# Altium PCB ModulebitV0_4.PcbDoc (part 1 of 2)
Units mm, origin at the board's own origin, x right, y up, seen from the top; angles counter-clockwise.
Board outline 60 x 54 mm, 2 copper layers (Top Layer, Bottom Layer), stack 1.671 mm thick; 125 components, 87 nets, 543 pads, 469 vias.
Unrouted connection lines stored in the file: 1.
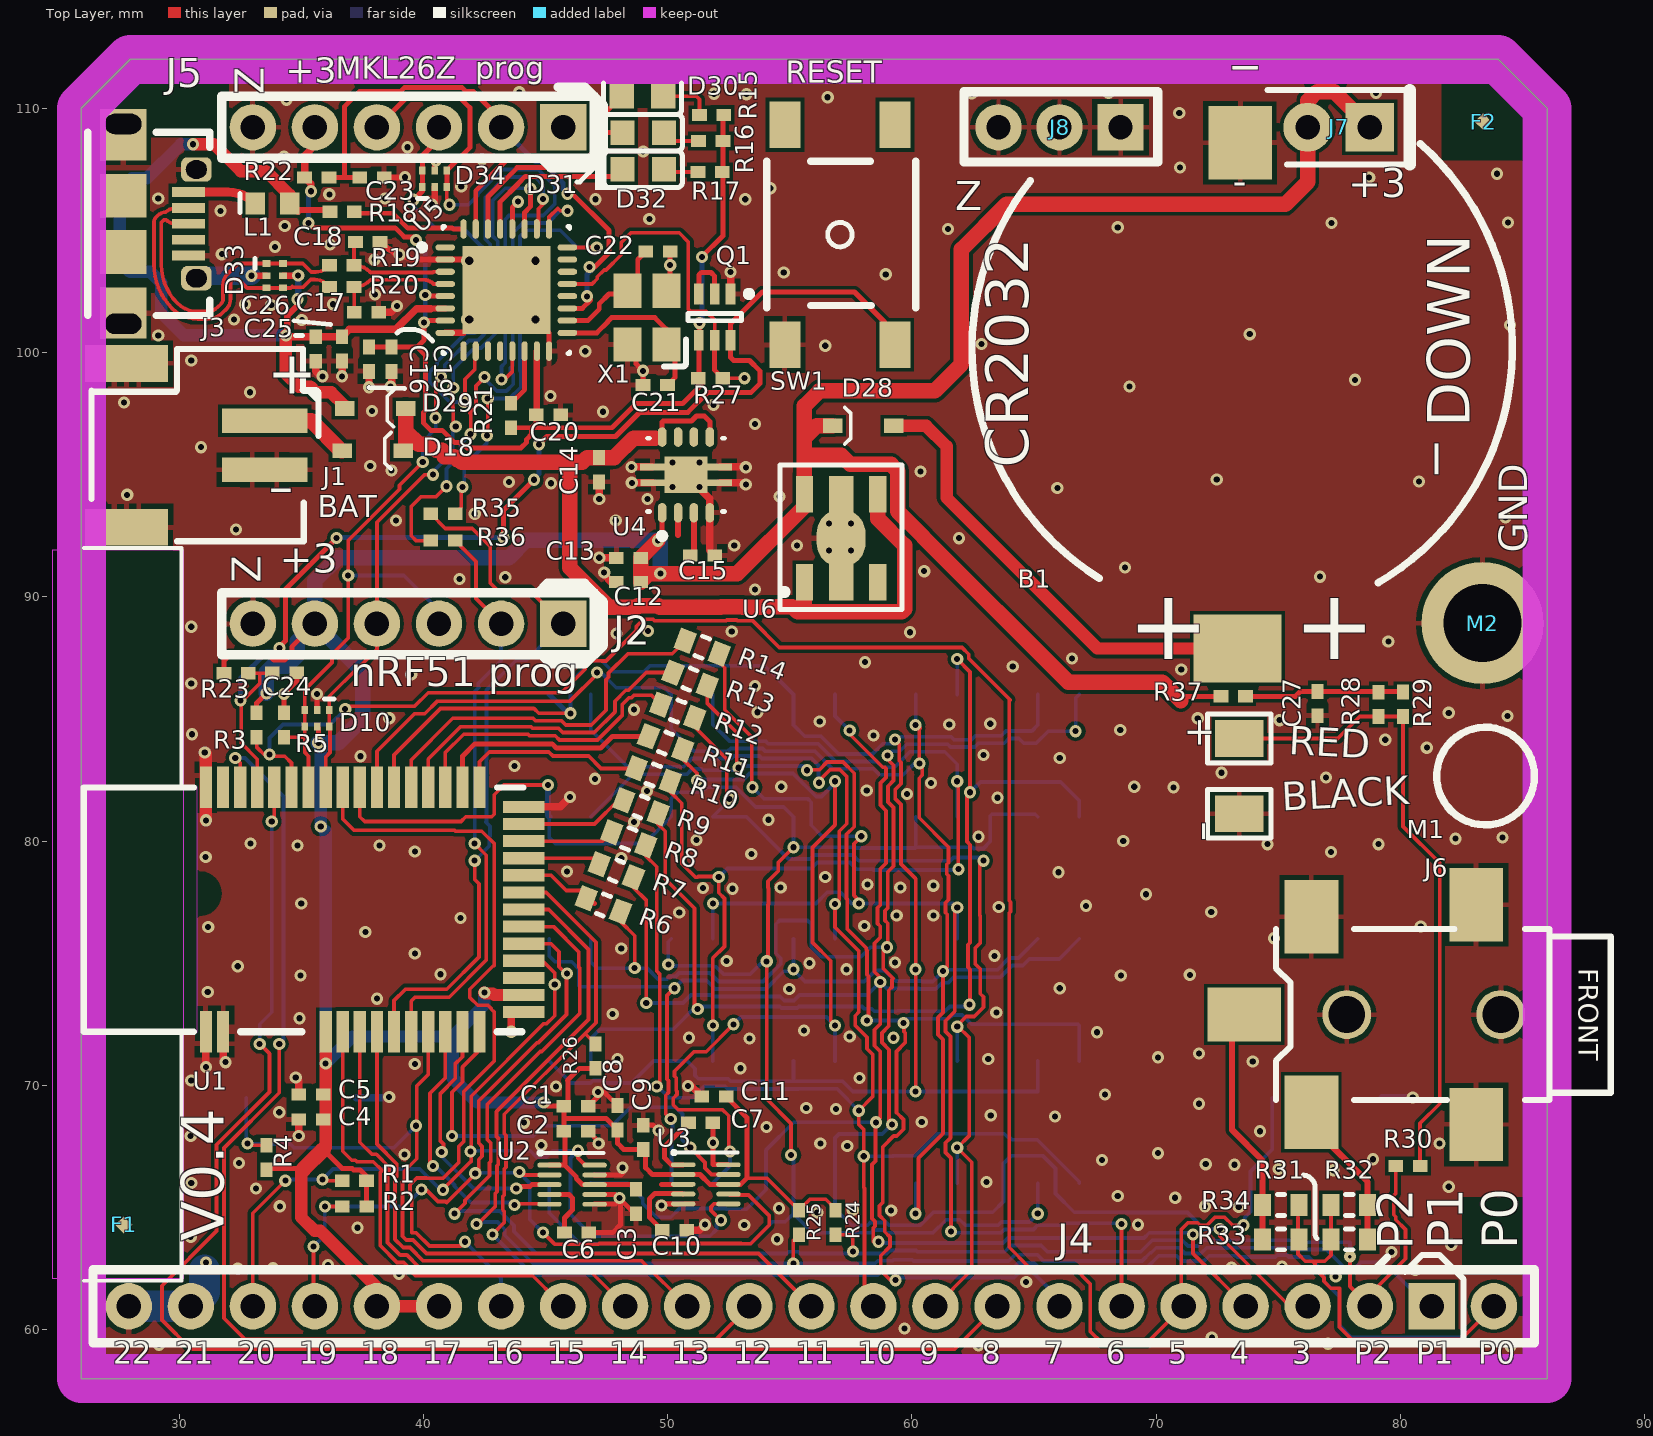
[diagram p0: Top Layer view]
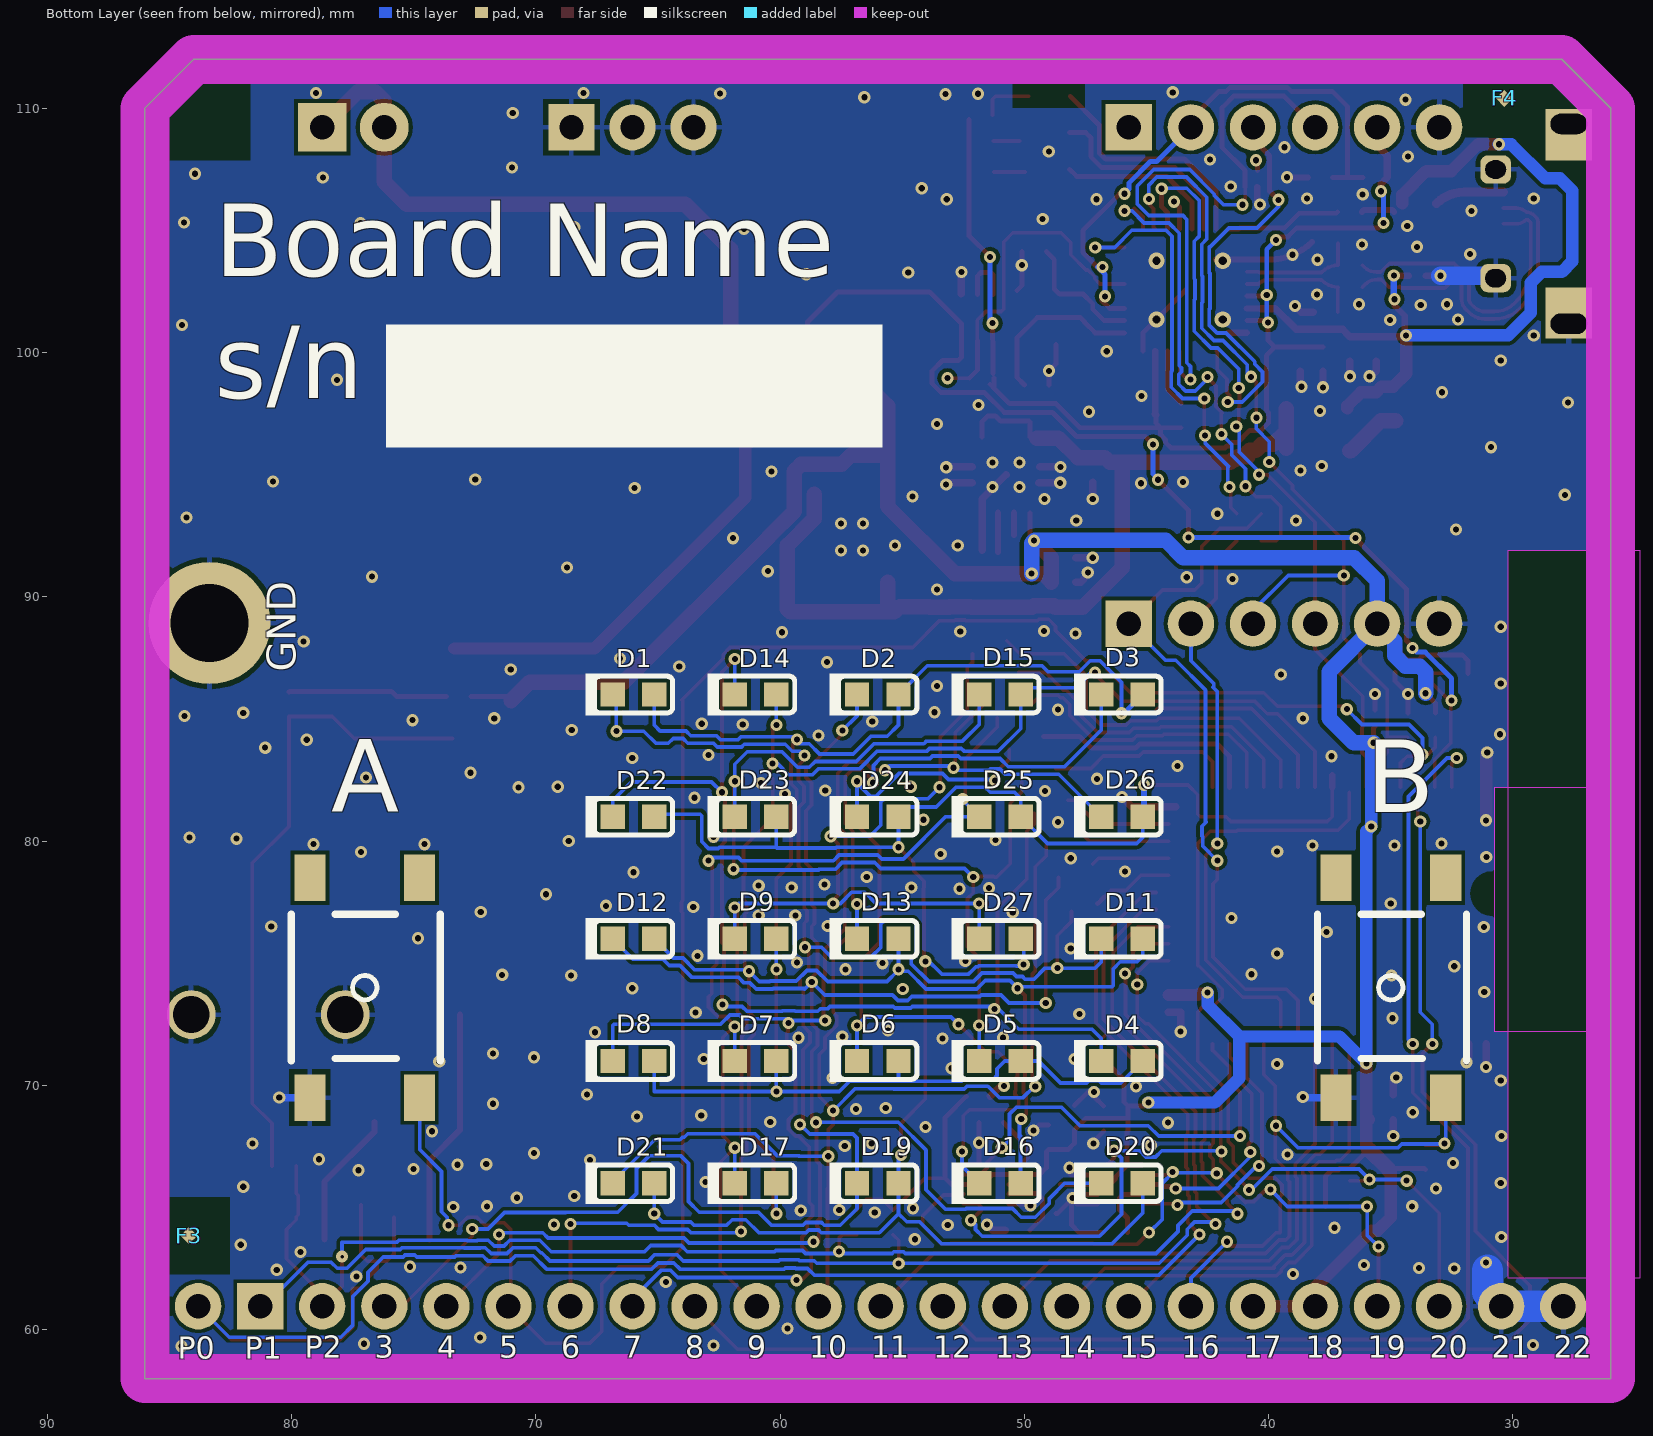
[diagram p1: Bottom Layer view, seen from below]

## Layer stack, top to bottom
Top Solder: solder mask 0.0102, Solder Resist, Dk 3.5
Top Layer: signal copper 0.0356
Dielectric 1: dielectric 1.6, FR-4, Dk 4.8
Bottom Layer: signal copper 0.0356
Bottom Solder: solder mask 0.0102, Solder Resist, Dk 3.5

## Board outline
26,58 86,58 86,110 84,112 28,112 26,110

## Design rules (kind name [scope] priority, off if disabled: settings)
Clearance Clearance_keepout [All vs (OnLayer('Keep-Out Layer'))] p1: gap=0.01
Clearance [All] p2: gap=0.152
DiffPairsRouting [All] p1: maxlimit=0.203 minlimit=0.152 mostfreqgap=0.152 toplayer_minwidth=0.152 toplayer_maxwidth=0.152 toplayer_prefwidth=0.152 bottomlayer_minwidth=0.152 bottomlayer_maxwidth=0.152 bottomlayer_prefwidth=0.152 maxuncoupledlength=12.7
MinimumAnnularRing [All] p1: minimumring=0.152
MinimumSolderMaskSliver [All] p1: minsoldermaskwidth=0.127
PlaneClearance [All] p1: clearance=0.254
PlaneConnect [All] p1: planeconnectstyle=Direct reliefexpansion=0.508 reliefentries=4 reliefconductorwidth=0.254 reliefairgap=0.254
PolygonConnect PolygonConnect_pad [ispad] p1: connectstyle=Relief reliefconductorwidth=0.203 reliefentries=4 polygonreliefangle="90 Angle" airgapwidth=0.203
PolygonConnect [All] p2: connectstyle=Direct reliefconductorwidth=0.203 reliefentries=4 polygonreliefangle="90 Angle" airgapwidth=0.203
RoutingVias [All] p1: holewidth=0.15 width=0.5 viastyle="Through Hole" minholewidth=0.15 minwidth=0.5 maxholewidth=1 maxwidth=2
SilkToSolderMaskClearance [IsPad] p1: minsilkscreentomaskgap=0.127 clearancetoexposedcopper=TRUE
SolderMaskExpansion [All] p1: expansion=0.051
Width [All] p1: maxlimit=2.54 minlimit=0.152 preferedwidth=0.152 minimp=50.000000 maximp=50.000000 favimp=50.000000
25 further rules are at their usual default settings.

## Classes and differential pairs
net class COL[1..9]: COL1 COL2 COL3 COL4 COL5 COL6 COL7 COL8 COL9
net class COLR[1..9]: COLR1 COLR2 COLR3 COLR4 COLR5 COLR6 COLR7 COLR8 COLR9
net class ROW[1..3]: ROW1 ROW2 ROW3
differential pair USB: +USB_P -USB_N
differential pair USB_D: +USB_D_P -USB_D_N

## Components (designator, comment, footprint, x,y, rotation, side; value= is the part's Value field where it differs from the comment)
A "SW_SPST_6MM" SW_FSM4JSMA#1 77,74 r0 bottom
B "SW_SPST_6MM" SW_FSM4JSMA#1 35,74 r0 bottom
B1 "BAT_CR2032_1" BAT_CR2032_CH7410-2032LF 73.43,100.184 r0 top
C1 "1U_6V3" C_0402 46.25,69.15 r90 top
C2 "CAP_100N_25V_0402_10%_X5R" C_0402 46.25,68.125 r90 top
C3 "CAP_100N_25V_0402_10%_X5R" C_0402 48.7,65.25 r0 top
C4 "1U_6V3" C_0402 35.4,68.6 r270 top
C5 "1U_6V3" C_0402 35.4,69.625 r270 top
C6 "CAP_100N_25V_0402_10%_X5R" C_0402 46.275,63.975 r90 top
C7 "CAP_100N_25V_0402_10%_X5R" C_0402 51.35,68.475 r90 top
C8 "1U_6V3" C_0402 47.95,68.675 r180 top
C9 "CAP_100N_25V_0402_10%_X5R" C_0402 49,67.875 r180 top
C10 "CAP_100N_25V_0402_10%_X5R" C_0402 50.275,64.075 r90 top
C11 "CAP_100N_25V_0402_10%_X5R" C_0402 51.9,69.55 r270 top
C12 "CAP_4U7_6V3_X5R_20%_0402" c_0402 48.395,90.602 r270 top
C13 "CAP_4U7_6V3_X5R_20%_0402" c_0402 48.395,91.592 r270 top
C14 "CAP_4U7_6V3_X5R_20%_0402" c_0402 47.193,95.199 r0 top
C15 "CAP_2.2nF_0402" C_0402 51.427,91.694 r90 top
C16 "1U_6V3" C_0402 37.775,99.725 r0 top
C17 "CAP_22pF_0402" c_0402 37.675,101.65 r90 top
C18 "CAP_22pF_0402" c_0402 37.725,104.525 r90 top
C19 "1U_6V3" C_0402 38.7,99.725 r0 top
C20 "1U_6V3" C_0402 45.118,97.453 r90 top
C21 "CAP_12PF_25V_0402" C_0402 49.492,98.671 r270 top
C22 "CAP_12PF_25V_0402" C_0402 49.602,104.132 r90 top
C23 "CAP_100N_25V_0402_10%_X5R" C_0402 37.897,107.169 r90 top
C24 "CAP_100N_25V_0402_10%_X5R" C_0402 34.319,86.893 r90 top
C25 "CAP_2.2nF_0402" C_0402 35.595,100.147 r0 top
C26 "1U_6V3" C_0402 36.675,100.15 r0 top
C27 "1U_6V3" C_0402 76.6,85.625 r0 top
D1 "LED_0603_RED" LED_0603_RED#1 66,86 r90 bottom
D2 "LED_0603_RED" LED_0603_RED#1 56,86 r90 bottom
D3 "LED_0603_RED" LED_0603_RED#1 46,86 r90 bottom
D4 "LED_0603_RED" LED_0603_RED#1 46,71 r90 bottom
D5 "LED_0603_RED" LED_0603_RED#1 51,71 r90 bottom
D6 "LED_0603_RED" LED_0603_RED#1 56,71 r90 bottom
D7 "LED_0603_RED" LED_0603_RED#1 61,71 r90 bottom
D8 "LED_0603_RED" LED_0603_RED#1 66,71 r90 bottom
D9 "LED_0603_RED" LED_0603_RED#1 61,76 r90 bottom
D10 "D_ESD_PRTR5V0U2F_115" SOT886 35.65,85.025 r270 top
D11 "LED_0603_RED" LED_0603_RED#1 46,76 r90 bottom
D12 "LED_0603_RED" LED_0603_RED#1 66,76 r90 bottom
D13 "LED_0603_RED" LED_0603_RED#1 56,76 r90 bottom
D14 "LED_0603_RED" LED_0603_RED#1 61,86 r90 bottom
D15 "LED_0603_RED" LED_0603_RED#1 51,86 r90 bottom
D16 "LED_0603_RED" LED_0603_RED#1 51,66 r90 bottom
D17 "LED_0603_RED" LED_0603_RED#1 61,66 r90 bottom
D18 "D_BAT60A_E6327" SOD323 37.922,95.98 r270 top
D19 "LED_0603_RED" LED_0603_RED#1 56,66 r90 bottom
D20 "LED_0603_RED" LED_0603_RED#1 46,66 r90 bottom
D21 "LED_0603_RED" LED_0603_RED#1 66,66 r90 bottom
D22 "LED_0603_RED" LED_0603_RED#1 66,81 r90 bottom
D23 "LED_0603_RED" LED_0603_RED#1 61,81 r90 bottom
D24 "LED_0603_RED" LED_0603_RED#1 56,81 r90 bottom
D25 "LED_0603_RED" LED_0603_RED#1 51,81 r90 bottom
D26 "LED_0603_RED" LED_0603_RED#1 46,81 r90 bottom
D27 "LED_0603_RED" LED_0603_RED#1 51,76 r90 bottom
D28 "D_BAT43WS-7-F" SOD323 58,97 r90 top
D29 "D_BAT60A_E6327" SOD323 38.024,97.707 r270 top
D30 "LED_0603_GREEN" LED_0603_GREEN 48.971,110.49 r90 top
D31 "LED_0603_BLUE" LED_0603_BLUE 49,109 r90 top
D32 "LED_0603_RED" LED_0603_RED#2 49,107.5 r90 top
D33 "D_ESD_PRTR5V0U2F_115" SOT886 33.916,103.143 r0 top
D34 "D_ESD_PRTR5V0U2F_115" SOT886 40.462,107.112 r90 top
F1 "FIDUCIAL" FIDUCIAL_OV 27.737,64.287 r90 top
F2 "FIDUCIAL" FIDUCIAL_OV 83.375,109.45 r90 top
F3 "FIDUCIAL" FIDUCIAL_OV 84.2,63.85 r90 bottom
F4 "FIDUCIAL" FIDUCIAL_OV 30.35,110.4 r90 bottom
J1 "CON_JST_2MM_2W_SMD_H" CON_JST_S2B-PH-SM4-TB 33.5,97.2 r270 top
J2 "CON_HDR_6X1_0.1IN" CON_HDR_6X1 45.72,88.9 r270 top locked
J3 "CON_USB_MICRO_AB_MOLEX" CON_USB_MICRO_AB_MOLEX 26.259,105.266 r270 top
J4 "CON_HDR_23X1" CON_HDR_23X1 81.28,60.96 r270 top locked
J5 "CON_HDR_6X1_0.1IN" CON_HDR_6X1 45.72,109.22 r270 top locked
J6 "CON_JACK_STEREO_3.5MM_SMD" CON_JACK_STEREO_3.5MM_SMT 86.1,72.9 r270 top
J7 "CON_HDR_2X1_0.1IN" CON_HDR_2X1 78.74,109.22 r180 top
J8 "CON_HDR_3X1_0.1IN" CON_HDR_3X1 68.538,109.22 r270 top
L1 "L_FERRITE_600R_400mA" L_0603 32.95,106.1 r90 top
M1 "MIC_ABM-715-RC" MIC_ABM-715-RC 83.48,82.66 r270 top locked
M2 "HOLE_3.2MM_DIA" HOLE_3.2MM_DIA 83.35,88.925 r90 top
Q1 "TR_PNP_NPN_PUMD9" SOT363_N 51.925,101.45 r270 top
R1 "R_1K_0402_5%" R_0402 37.175,66.1 r270 top
R2 "R_1K_0402_5%" R_0402 37.178,65.043 r270 top
R3 "R_1K_0402_5%" R_0402 33.175,84.75 r0 top
R4 "R_1K_0402_5%" R_0402 33.575,67.05 r180 top
R5 "R_12K_0402_1%" R_0402 34.3,84.75 r180 top
R6 "R_220R_0603_1%" R_0603 47.368,77.386 r249 top
R7 "R_220R_0603_1%" R_0603 47.905,78.786 r249 top
R8 "R_220R_0603_1%" R_0603 48.407,80.093 r249 top
R9 "R_220R_0603_1%" R_0603 48.909,81.4 r249 top
R10 "R_220R_0603_1%" R_0603 49.41,82.707 r249 top
R11 "R_220R_0603_1%" R_0603 49.912,84.014 r249 top
R12 "R_220R_0603_1%" R_0603 50.414,85.321 r249 top
R13 "R_220R_0603_1%" R_0603 50.915,86.628 r249 top
R14 "R_220R_0603_1%" R_0603 51.417,87.935 r249 top
R15 "R_1K_0402_5%" R_0402 51.8,109.725 r270 top
R16 "R_1K_0402_5%" R_0402 51.765,108.661 r270 top
R17 "R_1K_0402_5%" R_0402 51.74,107.391 r270 top
R18 "R_4K7_0402_5%" R_0402 36.678,105.759 r90 top
R19 "R_33R_0402_5%" R_0402 36.66,103.575 r90 top
R20 "R_33R_0402_5%" R_0402 36.66,102.676 r90 top
R21 "R_1K_0402_5%" R_0402 43.586,97.42 r180 top
R22 "R_10K_0402_5%" R_0402 35.636,107.163 r90 top
R23 "R_10K_0402_5%" R_0402 32.337,86.868 r90 top
R24 "R_10M_0402_5%" R_0402 56.871,64.389 r0 top
R25 "R_10M_0402_5%" R_0402 55.372,64.389 r0 top
R26 "R_10M_0402_5%" R_0402 47.041,71.196 r180 top
R27 "R_10K_0402_5%" R_0402 51.75,98.95 r90 top
R28 "R_4K7_0402_5%" R_0402 79.1,85.6 r0 top
R29 "R_4K7_0402_5%" R_0402 80.1,85.6 r0 top
R30 "R_1K_0402_5%" R_0402 80.3,66.7 r90 top
R31 "R_220R_0603_1%" R_0603 77.9,63.7 r270 top
R32 "R_220R_0603_1%" R_0603 77.9,65.1 r270 top
R33 "R_220R_0603_1%" R_0603 75.1,63.7 r90 top
R34 "R_220R_0603_1%" R_0603 75.1,65.1 r90 top
R35 "R_1K_0402_5%" R_0402 40.8,93.4 r90 top
R36 "R_1K_0402_5%" R_0402 40.8,92.3 r270 top
R37 "R_1K_0402_5%" R_0402 73.15,85.925 r90 top
SW1 "SW_SPST_6MM" SW_FSM4JSMA#2 57.05,104.825 r180 top
U1 "IC_nRF51822_MODULE" IC_nRF51822_MODULE_PASTE 35.949,76.99 r90 top
U2 "IC_MMA8653FCR1" IC_QFN40P200X200X85-10M 46.087,65.936 r0 top
U3 "IC_MAG3110FCR1" IC_QFN40P200X200X85-10M 51.562,65.951 r0 top
U4 "IC_TPS73533DRBR" IC_QFN65P300X300X100-8M-TI 50.749,94.991 r90 top
U5 "IC_MKL26Z128VFM4" IC_QFN50P500X500X100-32N 43.394,102.556 r0 top locked
U6 "IC_XC6227C331PR-G" SOT895 55.627,90.622 r90 top
X1 "XTAL_16MHZ_3.2X2.5MM" XTAL_3.2X2.5MM 49.15,101.425 r90 top

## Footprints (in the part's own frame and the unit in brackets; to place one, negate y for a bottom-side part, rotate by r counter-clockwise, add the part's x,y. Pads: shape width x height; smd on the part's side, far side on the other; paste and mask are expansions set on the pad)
BAT_CR2032_CH7410-2032LF [mm] "PLASTIC CR2032 HOLDER"
  rect 2.6x3 smd paste-2: NEG(0,8.4)
  rect 3.6x2.8 smd: POS1(-0.1,-12.3)
  silkscreen extent 5.65,-9.61 11.15,8.36, body extent -8,-13.4 8,10.85, height 5.4
C_0402 [mm]
  rect 0.5x0.6 smd: 1(0,0.5) 2(0,-0.5)
  body extent -0.26,-0.5 0.26,0.5, height 0.36
c_0402 [mm]
  rect 0.5x0.6 smd: 1(0,0.5) 2(0,-0.5)
  body extent -0.26,-0.5 0.26,0.5, height 0.36
CON_HDR_2X1 [mm]
  rect 2x2 hole 1: 1(0,0)
  round 2 hole 1: 2(2.54,0)
  silkscreen extent -1.64,-1.52 4.18,1.52, body extent -1.27,-1.27 3.81,1.27, height 8.41
CON_HDR_3X1 [mm]
  rect 1.9x1.9 hole 1: 1(0,0)
  round 1.9 hole 1: 2(0,-2.498) 3(0,-4.995)
  silkscreen extent -1.45,-6.41 1.42,1.52, body extent -1.27,-6.35 1.27,1.27, height 8.41
CON_HDR_6X1 [mm]
  rect 1.9x1.9 hole 1: 1(0,0)
  round 1.9 hole 1: 2(0,-2.54) 3(0,-5.08) 4(0,-7.62) 5(0,-10.16) 6(0,-12.7)
  silkscreen extent -1.65,-13.97 1.65,1.65, body extent -1.27,-13.93 1.27,1.27, height 8.41
CON_HDR_23X1 [mm]
  round 1.9 hole 1: 0(0,2.54) 2(0,-2.54) 3(0,-5.08) 4(0,-7.62) 5(0,-10.16) 6(0,-12.7) 7(0,-15.24) 8(0,-17.78) 9(0,-20.32) 10(0,-22.86) 11(0,-25.4) 12(0,-27.94) 13(0,-30.48) 14(0,-33.02) 15(0,-35.56) 16(0,-38.1) 17(0,-40.64) 18(0,-43.18) 19(0,-45.72) 20(0,-48.26) 21(0,-50.8) 22(0,-53.34)
  rect 1.9x1.9 hole 1: 1(0,0)
  silkscreen extent -2.1,-54.8 1.5,4.2, body extent -1.27,-54.61 1.27,3.81, height 8.41
CON_JACK_STEREO_3.5MM_SMT [mm] "CON_JACK_STEREO_SMT"
  rect 3x2.2 smd: BARL(-4,-9.75) P03(-4.5,-3) P04(4.5,-3) RING(4,-9.75)
  round 2 hole 1.5: P01(0,-2) P02(0,-8.3)
  rect 2.2x3 smd: TIP(0,-12.5)
  silkscreen extent -3.5,-11.2 3.5,2.5, body extent -5.1,-13.3 5.1,2.7, height 6
CON_JST_S2B-PH-SM4-TB [mm]
  oval 1x2 smd: 1(0,0.5) 1(0,-0.5) 2(2,-0.5) 2(2,0.5)
  rect 1x3.5 smd: 1(0,0) 2(2,0)
  rect 1.5x3.4 smd: P1(4.35,-5.65) P2(-2.35,-5.65)
  oval 1.5x2 smd: P1(4.35,-5.15) P1(4.35,-6.15) P2(-2.35,-6.15) P2(-2.35,-5.15)
  silkscreen extent -2.95,-7.09 4.93,2.21, body extent -2.97,-7.04 4.93,1.56, height 5.5
CON_USB_MICRO_AB_MOLEX [mm] "USB Micro-AB socket Molex 47589-0001"
  rect 0.4x1.35 smd: 1(-1.3,4.125) 2(-0.65,4.125) 3(0,4.125) 4(0.65,4.125) 5(1.3,4.125)
  rect 2.1x1.9 hole 0.83 slot 1.5 at 90 deg copper offset 0.44,0: H0(-4.09,1.45)
  rect 2.1x1.9 hole 0.83 slot 1.5 at 90 deg copper offset -0.44,0: H1(4.09,1.45)
  rrect50% 1x1.25 / inner rrect50% 1.15x1.25 / far side rrect50% 1.15x1.25 hole 0.75 slot 0.85 at 90 deg: H2(-2.225,4.45) H3(2.225,4.45)
  rect 1.8x1.9 smd: P0(-1.15,1.45) P1(1.15,1.45)
  silkscreen extent -3.75,0 3.75,5, body extent -4.35,-1.17 4.3,4.72, height 2.76
FIDUCIAL_OV [mm] "Fiducial for the overlord"
  rect 0.5x0.5 smd rot 45 paste-1 mask+0.2: 1(0,0)
  Top Layer pour cut-out: 154 vertices and 0 holes, not listed, extent -1,-1 1,1
  Top Layer pour cut-out: -1.6,-0.1 -1.6,-1.7 1.6,-1.7 1.6,1.7 -1.6,1.7
  Bottom Layer pour cut-out: -1.6,-0.1 -1.6,-1.7 1.6,-1.7 1.6,1.7 -1.6,1.7
HOLE_3.2MM_DIA [mm]
  round 5 hole 3.2: 1(0,0)
IC_nRF51822_MODULE_PASTE [mm] "IC_NRF51822_MODULE with extra paste dots as they are not very flat."
  round 0.5 smd: 1(-5.291,4.849) 1(-4.591,4.849) 2(-5.291,4.149) 2(-4.591,4.149) 3(-5.291,-0.051) 3(-4.591,-0.051) 4(-5.291,-0.751) 4(-4.591,-0.751) 5(-5.291,-1.451) 5(-4.591,-1.451) 6(-5.291,-2.151) 6(-4.591,-2.151) 7(-5.291,-2.851) 7(-4.591,-2.851) 8(-5.291,-3.551) 8(-4.591,-3.551) 9(-5.291,-4.251) 9(-4.591,-4.251) 10(-5.291,-4.951) 10(-4.591,-4.951) 11(-5.291,-5.651) 11(-4.591,-5.651) 12(-5.291,-6.351) 12(-4.591,-6.351) 13(-3.991,-8.651) 13(-3.991,-7.851) 14(-3.291,-8.651) 14(-3.291,-7.851) 15(-2.591,-8.651) 15(-2.591,-7.851) 16(-1.891,-7.851) 16(-1.891,-8.651) 17(-1.191,-8.651) 17(-1.191,-7.851) 18(-0.491,-7.851) 18(-0.491,-8.651) 19(0.209,-7.851) 19(0.209,-8.651) 20(0.909,-8.651) 20(0.909,-7.851) 21(1.609,-7.851) 21(1.609,-8.651) 22(2.309,-8.651) 22(2.309,-7.851) 23(3.009,-8.651) 23(3.009,-7.851) 24(3.709,-7.851) 24(3.709,-8.651) 25(4.409,-8.651) 25(4.409,-7.851) 26(5.009,-6.351) 26(5.709,-6.351) 27(5.009,-5.651) 27(5.709,-5.651) 28(5.009,-4.951) 28(5.709,-4.951) 29(5.009,-4.251) 29(5.709,-4.251) 30(5.009,-3.551) 30(5.709,-3.551) 31(5.009,-2.851) 31(5.709,-2.851) 32(5.009,-2.151) 32(5.709,-2.151) 33(5.009,-1.451) 33(5.709,-1.451) 34(5.009,-0.751) 34(5.709,-0.751) 35(5.009,-0.051) 35(5.709,-0.051) 36(5.009,0.649) 36(5.709,0.649) 37(5.009,1.349) 37(5.709,1.349) 38(5.009,2.049) 38(5.709,2.049) 39(5.009,2.749) 39(5.709,2.749) 40(5.009,3.449) 40(5.709,3.449) 41(5.009,4.149) 41(5.709,4.149) 42(5.009,4.849) 42(5.709,4.849)
  rect 1.7x0.5 smd: 1(-4.791,4.849) 2(-4.791,4.149) 3(-4.791,-0.051) 4(-4.791,-0.751) 5(-4.791,-1.451) 6(-4.791,-2.151) 7(-4.791,-2.851) 8(-4.791,-3.551) 9(-4.791,-4.251) 10(-4.791,-4.951) 11(-4.791,-5.651) 12(-4.791,-6.351) 26(5.209,-6.351) 27(5.209,-5.651) 28(5.209,-4.951) 29(5.209,-4.251) 30(5.209,-3.551) 31(5.209,-2.851) 32(5.209,-2.151) 33(5.209,-1.451) 34(5.209,-0.751) 35(5.209,-0.051) 36(5.209,0.649) 37(5.209,1.349) 38(5.209,2.049) 39(5.209,2.749) 40(5.209,3.449) 41(5.209,4.149) 42(5.209,4.849)
  rect 0.5x1.7 smd: 13(-3.991,-8.151) 14(-3.291,-8.151) 15(-2.591,-8.151) 16(-1.891,-8.151) 17(-1.191,-8.151) 18(-0.491,-8.151) 19(0.209,-8.151) 20(0.909,-8.151) 21(1.609,-8.151) 22(2.309,-8.151) 23(3.009,-8.151) 24(3.709,-8.151) 25(4.409,-8.151)
  silkscreen extent -4.79,-8.15 5.21,9.85, body extent -4.89,-8.18 5.11,9.82, height 3.2
IC_QFN40P200X200X85-10M [mm] "QFN, 10-Leads, Body 2.00x2.00mm, Pitch 0.40mm, IPC Low Density"
  oval 1x0.2 smd: 1(-0.925,0.8) 2(-0.925,0.4) 3(-0.925,0) 4(-0.925,-0.4) 5(-0.925,-0.8) 6(0.925,-0.8) 7(0.925,-0.4) 8(0.925,0) 9(0.925,0.4) 10(0.925,0.8)
  silkscreen extent -1.4,1.2 1.3,1.4, body extent -1,-1 1,1, height 0.85
IC_QFN50P500X500X100-32N [mm] "QFN, 32-Leads, Body 5.2x5.2mm (max), Pitch 0.50mm, IPC Medium Density"
  oval 0.8x0.25 smd: 1(-2.5,1.75) 2(-2.5,1.25) 3(-2.5,0.75) 4(-2.5,0.25) 5(-2.5,-0.25) 6(-2.5,-0.75) 7(-2.5,-1.25) 8(-2.5,-1.75) 17(2.5,-1.75) 18(2.5,-1.25) 19(2.5,-0.75) 20(2.5,-0.25) 21(2.5,0.25) 22(2.5,0.75) 23(2.5,1.25) 24(2.5,1.75)
  oval 0.25x0.8 smd: 9(-1.75,-2.5) 10(-1.25,-2.5) 11(-0.75,-2.5) 12(-0.25,-2.5) 13(0.25,-2.5) 14(0.75,-2.5) 15(1.25,-2.5) 16(1.75,-2.5) 25(1.75,2.5) 26(1.25,2.5) 27(0.75,2.5) 28(0.25,2.5) 29(-0.25,2.5) 30(-0.75,2.5) 31(-1.25,2.5) 32(-1.75,2.5)
  rect 3.6x3.6 smd: 33(0,0)
  silkscreen extent -3.57,-2.6 2.6,2.6, body extent -2.5,-2.5 2.5,2.5, height 0.85
IC_QFN65P300X300X100-8M-TI [mm] "QFN, 8-Leads, Body 3.0x3.0mm (max), Pitch 0.65mm, IPC Low Density"
  oval 0.8x0.35 smd: 1(-1.55,0.975) 2(-1.55,0.325) 3(-1.55,-0.325) 4(-1.55,-0.975) 5(1.55,-0.975) 6(1.55,-0.325) 7(1.55,0.325) 8(1.55,0.975)
  rect 0.28x1.025 smd: 9(-0.325,1.346) 9(-0.325,-1.372) 9(0.325,1.372) 9(0.325,-1.372)
  rect 1.5x1.75 smd: 9(0,0)
  silkscreen extent -2.62,-1.58 1.5,1.58, body extent -1.5,-1.5 1.5,1.5, height 1
L_0603 [mm]
  rect 0.9x0.8 smd: 1(0,-0.175) 2(0,-1.575)
  silkscreen extent -0.37,0.45 0.41,0.45, body extent -0.61,-1.82 0.56,-0.01, height 1.11
LED_0603_BLUE [mm] "LED_0603_BLUE"
  round 0.152 on Top Overlay: 1(0,0)
  rect 1x1 smd paste+0 mask+0: A(0,-0.85) K(0,0.85)
  silkscreen extent -0.85,-1.6 0.85,1.97, body extent -0.53,-1.09 0.53,0.92, height 0.46
LED_0603_GREEN [mm] "LED_0603_GREEN"
  round 0.152 on Top Overlay: 1(0,0)
  rect 1x1 smd paste+0 mask+0: A(0,-0.85) K(0,0.85)
  silkscreen extent -0.85,-1.6 0.53,1.78, body extent -0.4,-0.81 0.4,0.81, height 1.1
LED_0603_RED#1 [mm] "LED_0603_RED"
  round 0.152 on Bottom Overlay: 0(0,0)
  rect 1x1 smd paste+0 mask+0: A(0,-0.85) K(0,0.85)
  silkscreen extent -0.85,-1.6 0.85,1.97, body extent -0.43,-0.84 0.37,0.78, height 1.1
LED_0603_RED#2 [mm] "LED_0603_RED"
  round 0.152 on Top Overlay: 0(0,0)
  rect 1x1 smd paste+0 mask+0: A(0,-0.85) K(0,0.85)
  silkscreen extent -0.85,-1.6 0.85,1.97, body extent -0.43,-0.84 0.37,0.78, height 1.1
MIC_ABM-715-RC [mm]
  rect 1.5x2 smd: BLACK(1.54,-10.08) RED(-1.54,-10.08)
  silkscreen extent -2.54,-11.38 2.54,2, body extent -2,-9.9 2,2, height 2.5
R_0402 [mm]
  rect 0.5x0.6 smd: 1(0,0.5) 2(0,-0.5)
  body extent -0.25,-0.47 0.25,0.53, height 0.35
R_0603 [mm]
  rect 0.9x0.7 smd: 1(0,0.75) 2(0,-0.75)
  silkscreen extent -0.43,-0.15 0.43,0.15, body extent -0.42,-0.75 0.43,0.8, height 0.45
SOD323 [mm]
  rect 0.6x0.8 smd: 1(0,1.25) 2(0,-1.25)
  silkscreen extent -0.75,0.5 0.75,0.75, body extent -0.68,-1.3 0.67,1.3, height 1.1
SOT363_N [mm] "SOT363, 6-Leads, Body 2x1.3mm, Pitch 0.65mm, Lead Span 2.1mm, IPC Medium Density"
  rect 0.85x0.4 smd: 1(-0.95,0.65) 2(-0.95,0) 3(-0.95,-0.65) 4(0.95,-0.65) 5(0.95,0) 6(0.95,0.65)
  silkscreen extent -1.07,-1.1 0.15,1.53, body extent -1.2,-1.1 1.2,1.1, height 1.1
SOT886 [mm]
  rect 0.325x0.27 smd: 1(-0.337,0.5) 2(-0.337,0) 3(-0.337,-0.5) 4(0.337,-0.5) 5(0.337,0) 6(0.337,0.5)
  silkscreen extent -0.8,0.3 -0.8,0.7, body extent -0.5,-0.75 0.5,0.75, height 0.82
SOT895 [mm] "SOT-895"
  rect 1.5x0.7 smd: 1(-0.022,0.027) 3(-0.022,-2.973) 4(3.578,-2.973) 5(3.578,0.027)
  rect 1.5x1 smd: 2(-0.022,-1.473) 2(3.578,-1.473)
  oval 2.4x2 smd: 2(1.778,-1.473)
  silkscreen extent -1.14,-3.97 4.78,1.03, body extent -0.4,-3.75 3.9,0.75, height 1.5
SW_FSM4JSMA#1 [mm] "TE 6MM SPST SWITCH"
  rect 1.27x1.905 smd: 1(-2.25,4.5) 2(2.25,4.5) 3(2.25,-4.5) 4(-2.25,-4.5)
  round 0.152 on Bottom Overlay: 3(0,0)
  silkscreen extent -3.1,-3 3,3, body extent -3,-5 3,5, height 5.1
SW_FSM4JSMA#2 [mm] "TE 6MM SPST SWITCH"
  rect 1.27x1.905 smd: 1(-2.25,4.5) 2(2.25,4.5) 3(2.25,-4.5) 4(-2.25,-4.5)
  round 0.152 on Top Overlay: 3(0,0)
  silkscreen extent -3.1,-3 3,3, body extent -3,-5 3,5, height 5.1
XTAL_3.2X2.5MM [mm]
  rect 1.4x1.15 smd: 1(-1.1,-0.8) 2(1.1,-0.8) 3(1.1,0.8) 4(-1.1,0.8)
  silkscreen extent -2,-1.6 -0.9,-0.7, body extent -1.6,-1.2 1.6,1.2, height 0.7

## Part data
A B SW1: "SPST SWITCH 6MM"
B1: "CR2032 battery in holder"
C1 C4 C5 C8 C16 C19 C20 C26 C27: library part CAP_1u_6V3_0402_10%_X6S, "CAP_1u_6V3_0402_10%_X6S"
C17 C18: "CAP 0402 C0G 50V 22PF"
D1 D2 D3 D4 D5 D6 D7 D8 D9 D11 D12 D13 D14 D15 D16 D17 D19 D20 D21 D22 D23 D24 D25 D26 D27 D32: "LED RED 0603"
D10 D33 D34: "Ultra low capacitance double rail-to-rail ESD protection"
D18 D29: "3A Schottky diode with extreme low V  F drop (typ. 0.12V at IF = 10mA)"
D28: "Schottky 200mA 30V 0.5uA@25Vr"
F1 F2 F3 F4: "FIDUCIAL - NO CONNECT"
J1: "2 PIN 2MM SMT JST  CONNECTOR"
J2 J5: "6 PIN HEADER"
J3: "USB Micro-AB socket Molex 47589-0001"
J4: "0.1in HEADER STRIP 23X1"
J6: "3.5 MM STEREO SMT JACK SOCKET SMD"
J7: "2 PIN HEADER"
J8: "3 PIN HEADER"
L1: "FERRITE 600R 400mA 0.35R  IN 0603"
M1: "PRO SIGNAL  ABM-715-RC  ELECTRET MICROPHONE OMNI LEADS"
M2: "HOLE, 3.2MM DIA FINISHED"
Q1: "NXP - PUMD9 - TRANSISTOR, DIGITAL, NPN+PNP SOT-363"
U1: "RF System on a Chip - SoC 2.4GHz BT low Energy 256KB Flash 16KB Ram"
U2: "3-Axis 10-bit Digital  Accelerometer"
U3: "Three-Axis Digital  Magnetometer"
U4: "TPS735 500-mA 3V3, Low Quiescent Current, Ultra-Low Noise, High PSRR,  Low-Dropout Linear Regulator"
U5: "32bit ARM Cortex M0+ Microcontroller 48MHz 128 kB Flash 32-Pin QFN"
U6: "Linear Voltage Regulator IC Positive Fixed 1 Output 3.3V 700mA SOT-89-5"
X1: "CRYSTAL 16MHZ 20PF_3.2X2.5MM"

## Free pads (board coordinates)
  round 0.152 smd: 2(48.062,65.337)
  round 1.8 on Keep-Out: 5(30.85,77.85)

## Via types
v1: diameter 0.5, hole 0.25, Top Layer to Bottom Layer, tented both sides, 464 vias
v2: diameter 0.66, hole 0.33, Top Layer to Bottom Layer, tented both sides, 4 vias
v3: diameter 0.5, hole 0.15, Top Layer to Bottom Layer, 1 vias

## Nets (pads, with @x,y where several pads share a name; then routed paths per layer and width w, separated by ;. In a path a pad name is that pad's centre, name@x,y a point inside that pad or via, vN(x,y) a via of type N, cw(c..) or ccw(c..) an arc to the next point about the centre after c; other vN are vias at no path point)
ACC_INT1: U1.11 U2.3 | length 10.3
  Top Layer w0.152: v1(40.75,67.275) 40.825,67.2 40.825,67.598 40.696,67.727 40.696,69.671 41.3,70.275 41.3,70.875 41.6,71.174 U1.11@41.6,71.699
  Top Layer w0.203: v1(43.802,65.778) 43.802,65.859 44.359,65.859 44.436,65.936 U2.3@45.162,65.936
  Bottom Layer w0.152: v1(40.75,67.275) 40.75,67.075 42.047,65.778 v1(43.802,65.778)
ACC_INT2: U1.10 U2.5 | length 10.5
  Top Layer w0.152: v1(40.4,66.7) 40.425,66.7 40.271,66.854 40.271,69.677 40.9,70.306 U1.10@40.9,71.699 ; v1@43.957,65.15 U2.5@45.098,65.15
  Bottom Layer w0.152: v1(40.4,66.7) 40.502,66.7 41.279,65.923 41.279,65.871 41.94,65.21 43.62,65.21 v1(43.727,65.103)
BTN_A: A.1 J4.5 R3.2 U1.37 | length 82.5
  Top Layer w0.152: R3.2@33.175,84.25 33.175,83.85 v1@33.55,83.475 ; v1@33.7,83.475 34.325,83.475 34.6,83.2 U1.37@34.6,82.699 U1.37@34.6,82.199 ; v1(36.8,85.4) 36.917,85.517 39.642,85.517 40.2,86.075 45.65,86.075 46.624,87.049 46.624,87.102 46.904,87.383 47.301,87.383 47.308,87.375 47.475,87.375 48.721,88.621 48.721,88.798 49.002,89.079 49.398,89.079 49.452,89.025 52.398,89.025 52.427,89.054 52.823,89.054 52.852,89.025 53.475,89.025 54.571,87.929 62.048,87.929 62.329,87.648 62.329,87.471 63.979,85.821 ; 64.02,85.78 63.979,85.821 ; v1(73.575,64.275) 73.127,64.275 72.798,64.604 72.402,64.604 72.073,64.275 71.802,64.275 71.698,64.379 71.302,64.379 71.021,64.098 71.021,61.059 J4.5@71.12,60.96 69.61,59.45 67.775,59.45 67.3,59.925 67.3,61.875 66.6,62.575 64.775,62.575 63.979,63.371 63.979,77.052 64.032,77.106 64.032,77.502 63.979,77.555 63.979,85.821
  Bottom Layer w0.152: v1(33.7,83.55) 33.7,84.225 34.25,84.775 36.175,84.775 v1(36.8,85.4) ; v1(73.575,64.275) 73.625,64.325 73.625,64.598 73.854,64.827 73.854,66.479 74.75,67.375 A.1@74.75,69.5
BTN_B: B.1 J4.11 R4.2 U1.9 | length 35.8
  Top Layer w0.152: v1(32.8,67.625) 32.875,67.55 R4.2@33.575,67.55 ; U1.9@40.2,71.699 40.2,70.45 39.725,69.975 39.725,66.998 39.217,66.49 39.217,66.131 39.145,66.06 39.145,63.824 39.301,63.668 39.577,63.668 40.124,63.121 53.719,63.121 J4.11@55.582,61.257
  Bottom Layer w0.152: v1@32.75,67.625 B.1@32.75,69.5 ; v1@32.8,67.6 34.548,67.6 34.702,67.446 38.796,67.446 v1(39.7,68.35)
COL1: R6.2 U1.21 | length 3.4
  Top Layer w0.152: U1.21@44.1,78.599 U1.21@44.6,78.599 45.226,78.599 45.85,77.975 46.466,77.975 R6.2@46.727,77.714
  Top Layer w0.203: R6.2@46.727,77.714 47.001,77.44
COL2: R7.2 U1.22 | length 3.2
  Top Layer w0.152: U1.22@44.1,79.299 U1.22@44.6,79.299 46.961,79.299 R7.2@47.205,79.055
COL3: R8.2 U1.23 | length 3.8
  Top Layer w0.152: U1.23@44.1,79.999 U1.23@44.6,79.999 47.344,79.999 R8.2@47.707,80.362
COL4: R9.2 U1.24 | length 4.5
  Top Layer w0.152: U1.24@44.1,80.699 U1.24@44.6,80.699 47.01,80.699 47.979,81.669 R9.2@48.208,81.669
COL5: R10.2 U1.26 | length 7.9
  Top Layer w0.152: U1.26@42.3,82.199 U1.26@42.3,82.699 42.3,83.25 42.7,83.65 45.134,83.65 45.303,83.481 46.771,83.481 47.276,82.976 R10.2@48.71,82.976
COL6: R11.2 U1.27 | length 9.4
  Top Layer w0.203: U1.27@41.6,82.199 41.6,83.475 42.105,83.98 45.27,83.98 45.44,83.811 47.261,83.811 47.733,84.283 R11.2@49.212,84.283
COL7: R12.2 U1.28 | length 11.8
  Top Layer w0.152: U1.28@40.9,82.199 U1.28@40.9,82.699 40.9,83.625 41.65,84.375 44.28,84.375 44.34,84.315 45.403,84.315 45.577,84.141 47.124,84.141 48.146,85.163 48.146,85.598 48.415,85.867 48.524,85.867 48.633,85.975 49.329,85.975 R12.2@49.714,85.59
COL8: R13.2 U1.29 | length 13.1
  Top Layer w0.152: U1.29@40.2,82.199 U1.29@40.2,82.699 40.2,83.356 41.524,84.68 44.406,84.68 44.466,84.62 45.529,84.62 45.703,84.446 46.998,84.446 47.842,85.29 47.842,85.724 48.289,86.171 48.398,86.171 49.124,86.897 R13.2@50.215,86.897
COL9: R14.2 U1.30 | length 15.4
  Top Layer w0.152: U1.30@39.5,82.199 U1.30@39.5,82.699 39.5,83.325 41.2,85.025 44.492,85.025 44.593,84.924 45.655,84.924 45.829,84.751 46.871,84.751 47.475,85.354 47.475,86.6 47.581,86.706 47.581,86.881 48.371,87.671 50.184,87.671 R14.2@50.717,88.204
COLR1: D1.K D11.K D19.K J4.3 R6.1 | length 76.4
  Top Layer w0.152: R6.1@48.068,77.117 48.068,76.707 48.65,76.125 v1(48.65,74.8) ; v1@58.925,83.425 59.172,83.178 ; v1(58.978,75.654) 58.824,75.5 58.824,74.784 59.233,74.375 59.181,74.323 59.181,74.03 59.05,73.899 59.05,72.427 58.771,72.148 58.771,71.752 59.063,71.46 59.063,68.518 v1(59.178,68.403) ; v1@59.008,75.654 59.008,76.64 58.896,76.752 58.896,77.148 59.008,77.26 59.008,78.733 59.245,78.97 59.245,81.372 59.017,81.601 59.017,82.249 59.245,82.478 59.245,83.104 59.172,83.177 ; v1(72.6,64.125) 72.6,63.825 75.465,60.96 J4.3@76.2,60.96
  Bottom Layer w0.152: D11.K@46.85,76 46.85,75.05 47.1,74.8 v1(48.65,74.8) 49.15,74.8 49.611,74.339 49.963,74.339 50.077,74.454 50.323,74.454 50.466,74.597 51.729,74.597 52.076,74.25 53.902,74.25 54.625,74.973 54.625,75.202 54.421,75.405 54.421,76.595 54.577,76.75 55.723,76.75 55.879,76.595 55.879,75.648 56.255,75.271 57.921,75.271 58.304,75.654 v1(58.978,75.654) ; v1(58.998,83.502) 59.172,83.676 59.501,83.676 59.788,83.962 61.469,83.962 61.582,83.849 62.572,83.849 62.727,84.004 63.777,84.004 63.977,84.204 64.373,84.204 64.573,84.004 65.08,84.004 65.577,84.5 v1(66.7,84.5) 66.7,85.85 D1.K@66.85,86 ; v1(59.178,68.403) 58.783,68.009 57.009,68.009 56.85,67.85 D19.K@56.85,66 56.85,64.954 57.533,64.271 58.189,64.271 58.301,64.383 58.949,64.383 59.061,64.271 60.348,64.271 60.885,64.808 63.308,64.808 63.75,65.25 63.75,66.8 64.075,67.125 65.348,67.125 65.879,66.595 65.879,65.571 66.646,64.804 68.773,64.804 68.777,64.8 71.277,64.8 71.952,64.125 v1(72.6,64.125)
COLR2: D2.K D12.K D20.K J4.4 R7.1 | length 80.9
  Top Layer w0.152: R7.1@48.605,78.518 48.605,78.095 49.129,77.571 49.129,74.602 49.122,74.595 49.122,73.403 49.15,73.375 v1(49.125,73.375) ; v1(57.45,84.525) 57.45,84.373 58.8,83.023 58.895,83.023 58.94,82.978 58.94,82.604 58.712,82.376 58.712,81.474 58.94,81.246 58.94,79.096 58.704,78.86 58.704,77.386 58.592,77.274 58.592,76.626 58.704,76.514 58.704,76.056 58.467,75.819 58.467,74.651 v1@58.704,74.414 ; v1(58.625,63.6) 58.42,63.6 58.42,64.17 58.487,64.237 58.487,64.43 58.367,64.551 58.367,66.765 58.504,66.902 58.504,68.466 v1(58.525,68.487) 58.704,68.666 58.704,71.389 58.467,71.626 58.467,72.274 58.704,72.511 v1@58.704,74.226 ; v1(71.5,63.9) 71.5,63.12 J4.4@73.66,60.96
  Bottom Layer w0.152: D20.K@46.85,66 46.852,66.002 46.855,66 48.345,66 48.975,65.37 48.975,65.179 49.554,64.6 50.123,64.6 50.48,64.957 52.376,64.957 52.404,64.929 53.229,64.929 54.025,65.725 54.025,67.35 55.162,68.487 v1(58.525,68.487) ; v1(49.125,73.375) 50.625,73.375 50.95,73.7 51.764,73.7 51.824,73.64 54.608,73.64 54.777,73.471 55.173,73.471 55.402,73.7 58.174,73.7 v1(58.703,74.229) 58.986,73.945 59,73.945 59.022,73.967 60.278,73.967 60.3,73.945 60.976,73.945 61.227,74.196 61.473,74.196 61.709,74.432 63.624,74.432 64.101,74.908 64.533,74.908 64.8,75.175 66.025,75.175 D12.K@66.85,76 ; D2.K@56.85,86 56.85,85.125 v1(57.45,84.525) ; v1(58.625,63.6) 58.679,63.546 63.727,63.546 63.93,63.749 69.495,63.749 69.714,63.968 71.5,63.968 v1(71.5,63.9)
COLR3: D3.K D13.K D21.K J4.10 R8.1 | length 68
  Top Layer w0.152: R8.1@49.107,79.825 49.107,79.393 49.549,78.951 49.549,74.68 49.671,74.558 49.671,70.021 49.603,69.953 v1(49.552,69.953) ; v1(56.191,82.391) 56.114,82.391 56.652,82.929 57.048,82.929 57.329,82.648 57.329,80.712 57.02,80.403 57.02,77.596 v1(56.853,77.429) 56.853,76.472 57.825,75.5 57.825,73.003 57.674,72.852 57.674,72.455 58.162,71.968 58.162,71.499 58.399,71.262 58.399,69.54 v1(57.825,68.966) 57.825,68.4 58.025,68.2 v1(58.025,67.1) 58.025,65.825 58.062,65.788 58.062,61.318 J4.10@58.42,60.96
  Bottom Layer w0.152: D3.K@46.85,86 46.85,84.55 48.355,83.045 50.662,83.045 50.996,83.379 52.6,83.379 52.704,83.483 53.756,83.483 53.86,83.379 55.898,83.379 56.179,83.098 56.179,82.403 v1(56.191,82.391) ; v1(49.552,69.953) 49.597,69.953 50.05,69.5 51.026,69.5 51.492,69.967 52.347,69.967 52.464,69.85 55.342,69.85 55.351,69.858 56.933,69.858 v1(57.825,68.966) ; D13.K@56.85,76 56.853,76.003 v1(56.853,77.429) ; v1(58.025,67.1) 59.225,67.1 ; 59.225,67.125 60.125,67.125 61.025,68.025 63.777,68.025 63.924,67.878 63.997,67.878 64.1,67.775 65.129,67.775 66.85,66.054 D21.K@66.85,66
COLR4: D4.K D14.K D22.K R9.1 | length 47.8
  Top Layer w0.152: R9.1@49.609,81.132 49.609,80.691 49.9,80.4 49.9,78.45 51.102,77.248 51.102,73.223 51.196,73.129 v1(51.227,73.129) ; v1(61.85,87.45) 62.379,86.921 v1(62.379,82) 62.249,81.871 62.249,79.981 62.379,79.852 62.379,75.843 62.29,75.754 62.29,74.846 62.379,74.757 62.379,73.329 v1@62.354,73.304
  Bottom Layer w0.152: D4.K@46.85,71 46.85,71.925 47.225,72.3 50.225,72.3 51.129,73.204 51.204,73.129 v1(51.227,73.129) 51.227,73.152 51.152,73.227 51.158,73.233 54.584,73.233 54.651,73.167 55.299,73.167 55.366,73.233 57.954,73.233 58.055,73.132 58.351,73.132 58.452,73.031 59.379,73.031 59.4,73.052 59.9,73.052 59.921,73.031 61.355,73.031 61.558,73.233 62.283,73.233 v1(62.353,73.304) ; D14.K@61.85,86 v1(61.85,87.45) ; v1(62.379,82) 62.802,82.423 66.091,82.423 66.85,81.664 D22.K@66.85,81
COLR5: D5.K D15.K D23.K R10.1 | length 41.5
  Top Layer w0.152: R10.1@50.111,82.439 50.111,82.014 50.575,81.55 50.575,79.075 51.125,78.525 51.223,78.525 51.252,78.554 52.063,78.554 v1(52.092,78.525) 52.092,77.885 52.329,77.648 52.329,75.688 51.85,75.209 v1(51.85,72.45) ; v1(61.85,82.45) 61.9,82.4 v1(61.9,78.85)
  Bottom Layer w0.152: D5.K@51.85,71 v1(51.85,72.45) ; D15.K@51.85,86 51.85,84.775 52.533,84.092 54.009,84.092 54.113,83.988 56.151,83.988 56.878,83.261 58.562,83.261 58.8,83.023 59.28,83.023 59.914,83.658 61.342,83.658 61.85,83.15 v1(61.85,82.45) D23.K@61.85,81 ; v1(52.092,78.525) 52.45,78.883 55.882,78.883 56.126,79.127 57.459,79.127 57.743,78.843 58.402,78.843 58.425,78.82 61.87,78.82 v1(61.9,78.85)
COLR6: D6.K D16.K D24.K R11.1 | length 36.2
  Top Layer w0.152: R11.1@50.612,83.746 50.612,83.363 51.2,82.775 v1(51.2,82.475) ; v1(52.55,67.3) 52.496,67.354 52.496,68.754 52.25,69 50.433,69 50.23,69.203 50.23,69.472 50.383,69.626 50.383,69.746 50.349,69.78 50.349,70.309 50.281,70.377 50.281,70.581 51.075,71.375 51.575,71.375 v1(52.7,72.5) ; v1(56.85,72.45) 56.673,72.627 56.673,75.102 55.925,75.85 55.925,79.739 56.85,80.664 v1(56.85,82.45)
  Bottom Layer w0.152: v1(51.2,82.475) 51.25,82.525 53.101,82.525 53.344,82.769 55.135,82.769 56.083,81.821 56.298,81.821 v1@56.85,82.373 ; D16.K@51.85,66 52.55,66.7 v1(52.55,67.3) ; v1(52.7,72.5) 53,72.8 56.5,72.8 v1(56.85,72.45) D6.K@56.85,71 ; D24.K@56.85,81 v1@56.85,82.373 ; v1(56.85,82.45) v1@56.85,82.373
COLR7: D7.K D17.K D25.K J4.9 R12.1 | length 40.3
  Top Layer w0.152: R12.1@51.114,85.053 51.114,84.661 52.424,83.351 52.424,81.826 v1(52.525,81.725) ; J4.9@60.96,60.96 62.45,62.45 62.45,66.85 v1(61.85,67.45) 62.35,67.95 62.35,71.95 61.878,72.422 61.86,72.404 v1(61.853,72.404) 61.853,72.453 62.221,72.821 62.548,72.821 62.925,73.198 62.925,73.63 62.799,73.755 62.799,74.768 62.595,74.972 62.595,75.628 62.799,75.833 62.799,76.949 62.77,76.979 62.77,79.045 v1(62.925,79.2)
  Bottom Layer w0.152: v1(52.525,81.725) 52.525,81.675 D25.K@51.85,81 53.223,81 54.952,79.271 55.839,79.271 55.999,79.431 57.586,79.431 57.817,79.2 61.573,79.2 61.702,79.329 62.796,79.329 v1(62.925,79.2) ; D17.K@61.85,66 v1(61.85,67.45) ; D7.K@61.85,71 61.878,71.028 61.853,71.053 v1(61.853,72.404)
COLR8: D8.K D26.K J4.7 R13.1 | length 56.9
  Top Layer w0.152: R13.1@51.616,86.36 51.616,85.657 52.83,84.443 52.83,82.97 52.864,83.004 v1(52.903,83.004) ; v1@55.7,82.925 56.217,82.925 56.526,83.233 57.175,83.233 57.633,82.774 57.633,80.585 57.325,80.277 57.325,77.652 57.346,77.63 57.346,76.41 58.13,75.626 58.13,75.557 58.162,75.525 58.162,74.524 58.22,74.466 58.22,72.575 58.153,72.642 v1(58.153,72.654) ; v1(59.328,62.028) 59.122,62.028 58.725,62.425 58.725,63.023 59.104,63.402 59.104,63.798 58.888,64.014 58.888,64.46 58.671,64.677 58.671,65.073 58.808,65.21 58.808,67.483 59.25,67.925 59.376,67.925 59.656,68.205 59.656,68.602 59.376,68.882 59.368,68.882 59.368,71.391 59.729,71.752 59.729,72.148 59.675,72.202 59.675,72.6 59.653,72.578 v1(59.653,72.554)
  Bottom Layer w0.152: D26.K@46.85,81 48.59,82.74 50.789,82.74 51.002,82.954 51.398,82.954 51.452,82.9 52.742,82.9 52.916,83.074 55.526,83.074 v1(55.7,82.9) ; v1(58.153,72.654) 59.55,72.654 59.622,72.726 61.499,72.726 61.655,72.882 62.051,72.882 62.433,72.5 63.651,72.5 66.8,72.5 66.85,72.45 D8.K@66.85,71 ; v1@59.414,62.139 64.187,62.139 64.477,62.429 64.873,62.429 66.04,61.262 J4.7@66.04,60.96
COLR9: D9.K D27.K J4.6 R14.1 | length 52.4
  Top Layer w0.152: R14.1@52.117,87.667 52.117,87.308 52.332,87.093 52.332,85.371 53.446,84.258 53.446,82.204 v1(53.478,82.204) ; v1(57.825,77.45) 57.825,77.583 57.63,77.778 57.63,79.892 v1@57.938,80.2 ; v1(61.6,64.025) 61.6,67.023 61.371,67.252 61.371,67.648 61.575,67.852 61.575,69.144 61.58,69.149 61.58,72 61.371,72.208 61.371,72.648 61.754,73.03 61.754,77.354 61.828,77.279 v1(61.853,77.279) ; v1(68.575,64.325) 68.58,64.32 J4.6@68.58,60.96
  Bottom Layer w0.152: D27.K@51.85,76 v1(51.85,77.45) 56.075,77.45 56.532,77.907 57.069,77.907 57.527,77.45 v1(57.825,77.45) 61.682,77.45 v1(61.853,77.279) 61.853,76.003 D9.K@61.85,76 ; v1(53.478,82.204) 53.953,81.729 55.745,81.729 55.879,81.595 55.879,80.645 56.323,80.2 v1(57.925,80.2) ; v1(61.6,64.025) 61.658,63.967 63.644,63.967 63.782,64.105 64.975,64.105 65.141,64.271 66.193,64.271 66.275,64.354 68.546,64.354 v1(68.575,64.325)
